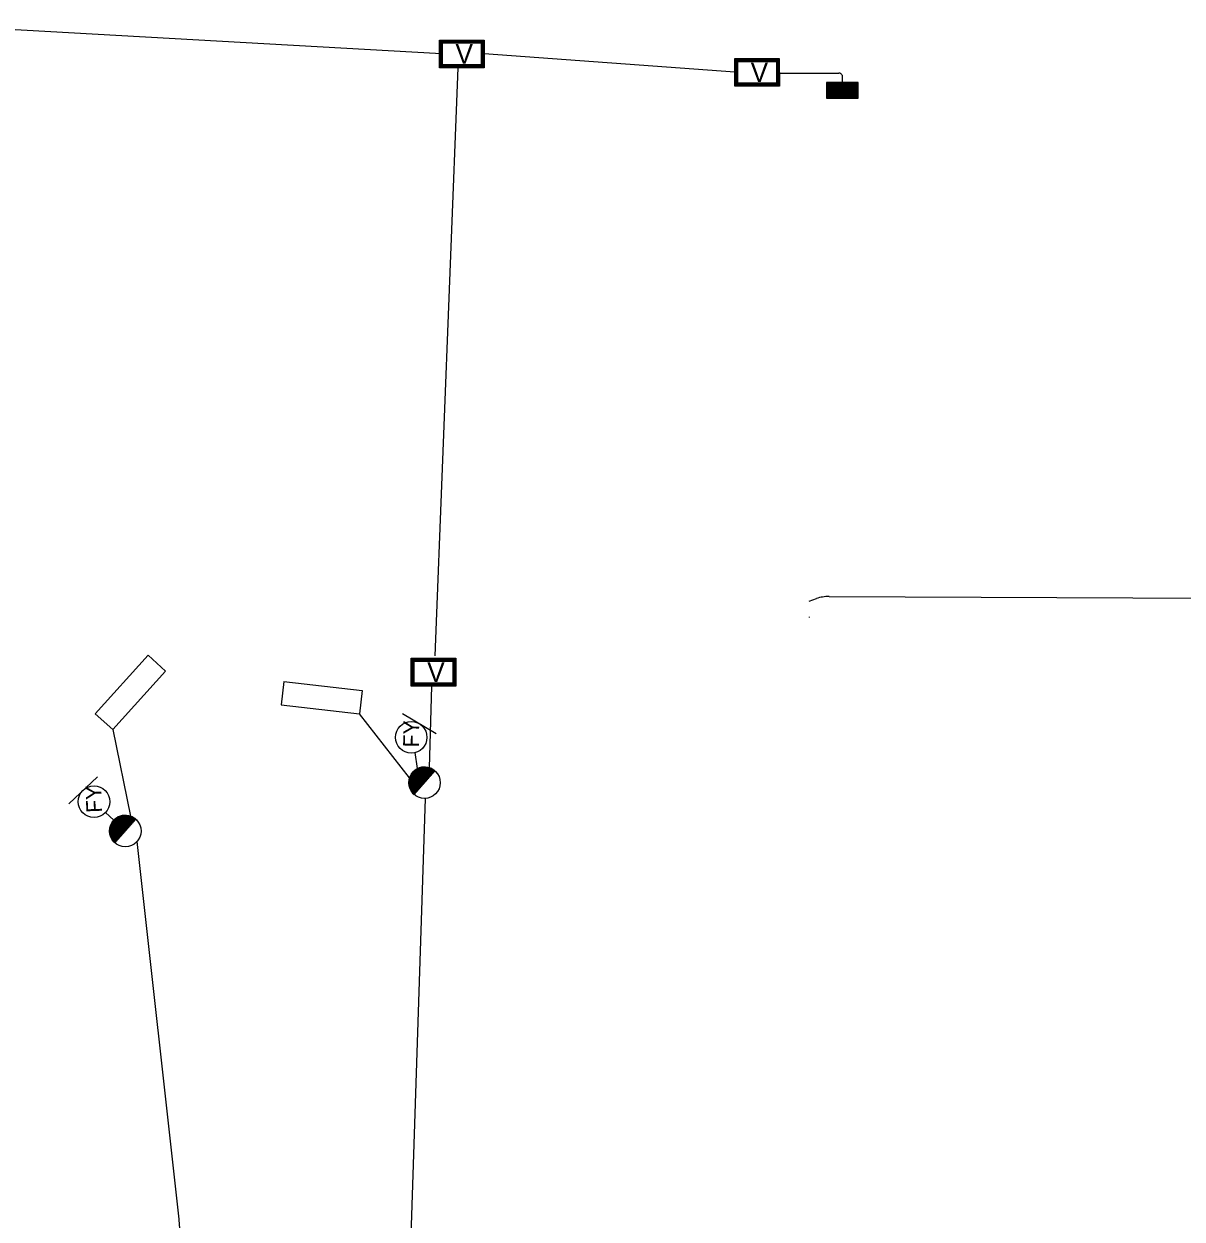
# Model space of a CAD drawing. Extents: x 584850 to 602551, y 145475 to 158627.
# Drawn here: x 585403.2 to 585697.1, y 152341.8 to 152645.2 of the extents above; entities that cross this region are included whole.
import ezdxf

# ---------------------------------------------------------------- set-up
doc = ezdxf.new("R2010")
doc.units = 0
doc.layers.add('Default', color=7, linetype='Continuous')

msp = doc.modelspace()

# ---------------------------------------------------------------- linework, layer by layer
at = {"layer": 'Default'}
for p, q in [((585509.18, 152637.61), (585374.01, 152645.23)), ((585583.59, 152632.95), (585519.98, 152637.62)), ((585507.52, 152484.81), (585513.42, 152634.09)), ((585594.9, 152632.75), (585609.97, 152632.76)), ((585606.87, 152626.36), (585610.87, 152630.36)), ((585606.87, 152628.05), (585609.18, 152630.36)), ((585606.87, 152629.75), (585607.48, 152630.36)), ((585606.87, 152626.7), (585610.53, 152630.36)), ((585606.87, 152628.39), (585608.84, 152630.36)), ((585606.87, 152630.09), (585607.14, 152630.36)), ((585606.87, 152627.04), (585610.2, 152630.36)), ((585606.87, 152628.73), (585608.5, 152630.36)), ((585606.87, 152627.37), (585609.86, 152630.36)), ((585606.87, 152629.07), (585608.16, 152630.36)), ((585606.87, 152627.71), (585609.52, 152630.36)), ((585606.87, 152629.41), (585607.82, 152630.36)), ((585610.61, 152626.36), (585606.87, 152630.09)), ((585610.27, 152626.36), (585606.87, 152629.75)), ((585610.95, 152626.36), (585606.95, 152630.36)), ((585607.21, 152626.36), (585611.21, 152630.36)), ((585611.29, 152626.36), (585607.29, 152630.36)), ((585607.55, 152626.36), (585611.55, 152630.36)), ((585611.63, 152626.36), (585607.63, 152630.36)), ((585607.89, 152626.36), (585611.89, 152630.36)), ((585611.97, 152626.36), (585607.97, 152630.36)), ((585608.23, 152626.36), (585612.23, 152630.36)), ((585612.3, 152626.36), (585608.3, 152630.36)), ((585608.57, 152626.36), (585612.57, 152630.36)), ((585612.64, 152626.36), (585608.64, 152630.36)), ((585608.91, 152626.36), (585612.91, 152630.36)), ((585612.98, 152626.36), (585608.98, 152630.36)), ((585609.25, 152626.36), (585613.25, 152630.36)), ((585613.32, 152626.36), (585609.32, 152630.36)), ((585609.59, 152626.36), (585613.59, 152630.36)), ((585613.66, 152626.36), (585609.66, 152630.36)), ((585609.93, 152626.36), (585613.93, 152630.36)), ((585614, 152626.36), (585610, 152630.36)), ((585610.27, 152626.36), (585614.27, 152630.36)), ((585614.34, 152626.36), (585610.34, 152630.36)), ((585610.61, 152626.36), (585614.61, 152630.36)), ((585614.68, 152626.36), (585610.68, 152630.36)), ((585610.95, 152626.36), (585614.87, 152630.28)), ((585610.97, 152630.36), (585610.97, 152631.76)), ((585614.87, 152626.5), (585611.02, 152630.36)), ((585611.29, 152626.36), (585614.87, 152629.94)), ((585614.87, 152626.84), (585611.36, 152630.36)), ((585614.87, 152627.18), (585611.7, 152630.36)), ((585614.87, 152627.52), (585612.04, 152630.36)), ((585614.87, 152627.86), (585612.38, 152630.36)), ((585614.87, 152628.2), (585612.72, 152630.36)), ((585614.87, 152628.54), (585613.06, 152630.36)), ((585614.87, 152628.88), (585613.4, 152630.36)), ((585614.87, 152629.22), (585613.74, 152630.36)), ((585614.87, 152629.56), (585614.07, 152630.36)), ((585614.87, 152629.9), (585614.41, 152630.36)), ((585614.87, 152630.24), (585614.75, 152630.36)), ((585609.93, 152626.36), (585606.87, 152629.41)), ((585609.59, 152626.36), (585606.87, 152629.07)), ((585609.25, 152626.36), (585606.87, 152628.73)), ((585608.91, 152626.36), (585606.87, 152628.39)), ((585608.57, 152626.36), (585606.87, 152628.05)), ((585608.23, 152626.36), (585606.87, 152627.71)), ((585607.89, 152626.36), (585606.87, 152627.37)), ((585607.55, 152626.36), (585606.87, 152627.04)), ((585611.63, 152626.36), (585614.87, 152629.6)), ((585611.97, 152626.36), (585614.87, 152629.27)), ((585612.3, 152626.36), (585614.87, 152628.93)), ((585612.64, 152626.36), (585614.87, 152628.59)), ((585612.98, 152626.36), (585614.87, 152628.25)), ((585613.32, 152626.36), (585614.87, 152627.91)), ((585613.66, 152626.36), (585614.87, 152627.57)), ((585614, 152626.36), (585614.87, 152627.23)), ((585614.34, 152626.36), (585614.87, 152626.89)), ((585607.21, 152626.36), (585606.87, 152626.7)), ((585614.68, 152626.36), (585614.87, 152626.55)), ((585602.45, 152498.72), (585604.3, 152499.35)), ((585607.54, 152499.87), (585794.95, 152498.99)), ((585602.45, 152494.72), (585602.45, 152494.58)), ((585421.27, 152470.08), (585434.66, 152484.94)), ((585434.66, 152484.94), (585439.11, 152480.93)), ((585425.73, 152466.07), (585439.11, 152480.93)), ((585469.13, 152478.3), (585468.44, 152472.34)), ((585469.13, 152478.3), (585489, 152476.01)), ((585489, 152476.01), (585488.31, 152470.05)), ((585506.13, 152456.36), (585506.67, 152477.13)), ((585468.44, 152472.34), (585488.31, 152470.05)), ((585421.27, 152470.08), (585425.73, 152466.07)), ((585501.05, 152453.87), (585488.31, 152470.05)), ((585507.8, 152464.99), (585499.21, 152470.11)), ((585425.73, 152466.07), (585430.18, 152444.1)), ((585503.07, 152456.17), (585502.44, 152460.24)), ((585421.81, 152454.12), (585414.57, 152447.22)), ((585505.96, 152453.85), (585500.96, 152453.53)), ((585506.18, 152454.1), (585501.03, 152453.78)), ((585506.41, 152454.36), (585501.12, 152454.02)), ((585501.13, 152454.06), (585501.35, 152450.64)), ((585506.63, 152454.61), (585501.22, 152454.27)), ((585501.35, 152454.5), (585501.62, 152450.22)), ((585506.85, 152454.87), (585501.36, 152454.52)), ((585507.08, 152455.12), (585501.5, 152454.77)), ((585501.56, 152454.87), (585501.88, 152449.89)), ((585507.3, 152455.38), (585501.69, 152455.02)), ((585501.79, 152455.14), (585502.14, 152449.63)), ((585507.42, 152455.62), (585501.89, 152455.27)), ((585502.01, 152455.4), (585502.37, 152449.77)), ((585507.12, 152455.85), (585502.16, 152455.53)), ((585502.19, 152449.57), (585507.48, 152455.58)), ((585502.24, 152455.6), (585502.59, 152450.03)), ((585506.77, 152456.06), (585502.46, 152455.79)), ((585502.47, 152455.8), (585502.82, 152450.28)), ((585502.7, 152455.94), (585503.04, 152450.54)), ((585506.34, 152456.28), (585502.89, 152456.06)), ((585502.93, 152456.08), (585503.26, 152450.79)), ((585503.16, 152456.2), (585503.49, 152451.05)), ((585503.4, 152456.29), (585503.71, 152451.3)), ((585505.7, 152456.48), (585503.51, 152456.34)), ((585503.63, 152456.39), (585503.94, 152451.56)), ((585503.87, 152456.44), (585504.16, 152451.81)), ((585504.11, 152456.5), (585504.39, 152452.07)), ((585504.34, 152456.54), (585504.61, 152452.32)), ((585504.58, 152456.55), (585504.84, 152452.58)), ((585504.82, 152456.56), (585505.06, 152452.83)), ((585505.06, 152456.56), (585505.28, 152453.08)), ((585505.31, 152456.53), (585505.51, 152453.34)), ((585505.55, 152456.5), (585505.73, 152453.59)), ((585505.79, 152456.45), (585505.96, 152453.85)), ((585506.04, 152456.37), (585506.18, 152454.1)), ((585506.28, 152456.3), (585506.41, 152454.36)), ((585506.53, 152456.18), (585506.63, 152454.61)), ((585506.78, 152456.06), (585506.85, 152454.87)), ((585507.03, 152455.91), (585507.08, 152455.12)), ((585507.28, 152455.72), (585507.3, 152455.38)), ((585507.44, 152455.6), (585507.45, 152455.54)), ((585505.28, 152453.08), (585500.85, 152452.8)), ((585505.06, 152452.83), (585500.85, 152452.56)), ((585504.84, 152452.58), (585500.85, 152452.32)), ((585505.51, 152453.34), (585500.87, 152453.05)), ((585504.61, 152452.32), (585500.88, 152452.08)), ((585505.73, 152453.59), (585500.91, 152453.29)), ((585504.39, 152452.07), (585500.92, 152451.85)), ((585500.93, 152453.41), (585501.07, 152451.27)), ((585504.16, 152451.81), (585500.96, 152451.61)), ((585503.94, 152451.56), (585501.03, 152451.37)), ((585503.71, 152451.3), (585501.12, 152451.14)), ((585503.49, 152451.05), (585501.2, 152450.9)), ((585503.26, 152450.79), (585501.33, 152450.67)), ((585498.86, 152257.42), (585505.09, 152448.58)), ((585503.04, 152450.54), (585501.46, 152450.44)), ((585502.82, 152450.28), (585501.62, 152450.21)), ((585502.59, 152450.03), (585501.81, 152449.98)), ((585502.37, 152449.77), (585502.01, 152449.75)), ((585502.19, 152449.57), (585502.19, 152449.58)), ((585502.19, 152449.57), (585502.19, 152449.58)), ((585426.02, 152443.1), (585423.89, 152445.07)), ((585430.23, 152441.84), (585425.08, 152441.51)), ((585430.46, 152442.09), (585425.17, 152441.76)), ((585425.18, 152441.8), (585425.4, 152438.38)), ((585430.68, 152442.35), (585425.27, 152442.01)), ((585425.4, 152442.24), (585425.67, 152437.95)), ((585430.9, 152442.6), (585425.41, 152442.26)), ((585431.13, 152442.86), (585425.55, 152442.5)), ((585425.61, 152442.6), (585425.93, 152437.63)), ((585431.35, 152443.11), (585425.74, 152442.76)), ((585425.84, 152442.88), (585426.19, 152437.36)), ((585431.46, 152443.36), (585425.94, 152443.01)), ((585426.06, 152443.14), (585426.42, 152437.51)), ((585431.17, 152443.58), (585426.21, 152443.27)), ((585426.24, 152437.31), (585431.53, 152443.31)), ((585426.29, 152443.34), (585426.64, 152437.76)), ((585430.82, 152443.8), (585426.51, 152443.53)), ((585426.52, 152443.53), (585426.87, 152438.02)), ((585426.75, 152443.68), (585427.09, 152438.27)), ((585430.39, 152444.01), (585426.94, 152443.8)), ((585426.98, 152443.82), (585427.31, 152438.53)), ((585427.21, 152443.93), (585427.54, 152438.78)), ((585427.45, 152444.03), (585427.76, 152439.04)), ((585429.75, 152444.21), (585427.56, 152444.08)), ((585427.68, 152444.12), (585427.99, 152439.29)), ((585427.92, 152444.18), (585428.21, 152439.55)), ((585428.16, 152444.23), (585428.44, 152439.8)), ((585428.39, 152444.28), (585428.66, 152440.06)), ((585428.63, 152444.29), (585428.88, 152440.31)), ((585428.87, 152444.3), (585429.11, 152440.57)), ((585429.11, 152444.3), (585429.33, 152440.82)), ((585429.36, 152444.27), (585429.56, 152441.08)), ((585429.6, 152444.24), (585429.78, 152441.33)), ((585429.84, 152444.19), (585430.01, 152441.58)), ((585430.09, 152444.11), (585430.23, 152441.84)), ((585430.33, 152444.04), (585430.46, 152442.09)), ((585430.58, 152443.92), (585430.68, 152442.35)), ((585430.83, 152443.79), (585430.9, 152442.6)), ((585431.08, 152443.65), (585431.13, 152442.86)), ((585431.33, 152443.46), (585431.35, 152443.11)), ((585431.49, 152443.34), (585431.5, 152443.28)), ((585429.33, 152440.82), (585424.9, 152440.54)), ((585429.11, 152440.57), (585424.9, 152440.3)), ((585428.88, 152440.31), (585424.9, 152440.06)), ((585429.56, 152441.08), (585424.92, 152440.78)), ((585428.66, 152440.06), (585424.93, 152439.82)), ((585429.78, 152441.33), (585424.96, 152441.03)), ((585428.44, 152439.8), (585424.97, 152439.58)), ((585424.98, 152441.15), (585425.12, 152439)), ((585430.01, 152441.58), (585425.01, 152441.27)), ((585428.21, 152439.55), (585425.01, 152439.34)), ((585427.99, 152439.29), (585425.08, 152439.11)), ((585427.76, 152439.04), (585425.17, 152438.87)), ((585427.54, 152438.78), (585425.25, 152438.64)), ((585427.31, 152438.53), (585425.38, 152438.41)), ((585427.09, 152438.27), (585425.51, 152438.17)), ((585426.87, 152438.02), (585425.67, 152437.94)), ((585426.64, 152437.76), (585425.86, 152437.71)), ((585426.42, 152437.51), (585426.06, 152437.49)), ((585426.24, 152437.31), (585426.24, 152437.31)), ((585426.24, 152437.31), (585426.24, 152437.31)), ((585442.54, 152341.82), (585431.89, 152437.67))]:
    msp.add_line(p, q, dxfattribs=at)
for points in [[(585508.68, 152641.14), (585519.98, 152641.14), (585519.99, 152634.09), (585508.68, 152634.09)], [(585508.93, 152640.89), (585519.73, 152640.89), (585519.74, 152634.34), (585508.93, 152634.34)], [(585509.18, 152640.64), (585519.48, 152640.64), (585519.49, 152634.59), (585509.18, 152634.59)], [(585509.43, 152640.39), (585519.23, 152640.39), (585519.24, 152634.84), (585509.43, 152634.84)], [(585583.59, 152636.47), (585594.89, 152636.47), (585594.9, 152629.43), (585583.59, 152629.43)], [(585583.84, 152636.22), (585594.64, 152636.22), (585594.65, 152629.68), (585583.84, 152629.68)], [(585584.09, 152635.97), (585594.39, 152635.97), (585594.4, 152629.93), (585584.09, 152629.93)], [(585584.34, 152635.72), (585594.14, 152635.72), (585594.15, 152630.18), (585584.34, 152630.18)], [(585614.87, 152630.36), (585606.87, 152630.36), (585606.87, 152626.36), (585614.87, 152626.36)], [(585501.49, 152484.18), (585512.8, 152484.18), (585512.8, 152477.14), (585501.49, 152477.13)], [(585501.74, 152483.93), (585512.55, 152483.93), (585512.55, 152477.39), (585501.74, 152477.38)], [(585501.99, 152483.68), (585512.3, 152483.68), (585512.3, 152477.64), (585501.99, 152477.63)], [(585502.24, 152483.43), (585512.05, 152483.43), (585512.05, 152477.89), (585502.24, 152477.88)]]:
    msp.add_lwpolyline(points, close=True, dxfattribs=at)
for centre in [(585501.46, 152464.11), (585504.84, 152452.58), (585420.95, 152447.78), (585428.88, 152440.31)]:
    msp.add_circle(centre, 4, dxfattribs=at)
for centre, radius, start, end in [((585609.97, 152631.76), 1, 0, 90.0146), ((585607.49, 152489.87), 10, 89.7316, 108.6271), ((585504.84, 152452.58), 4, 48.6166, 228.6166), ((585428.88, 152440.31), 4, 48.6166, 228.6166), ((585343.09, 152331.41), 100, 359.297, 5.9743)]:
    msp.add_arc(centre, radius, start, end, dxfattribs=at)

# ---------------------------------------------------------------- texts
for s, height, rotation, p in [('V', 4.96, 0.0146, (585512.71, 152635.13)), ('V', 4.96, 0.0146, (585587.62, 152630.47)), ('V', 4.96, 0.0146, (585505.53, 152478.18)), ('FY', 4, 89.079, (585503.4, 152461.55)), ('FY', 4, 92.1058, (585423.03, 152445.05))]:
    msp.add_text(s, height=height, rotation=rotation, dxfattribs=at).set_placement(p)

doc.saveas('drawing.dxf')
